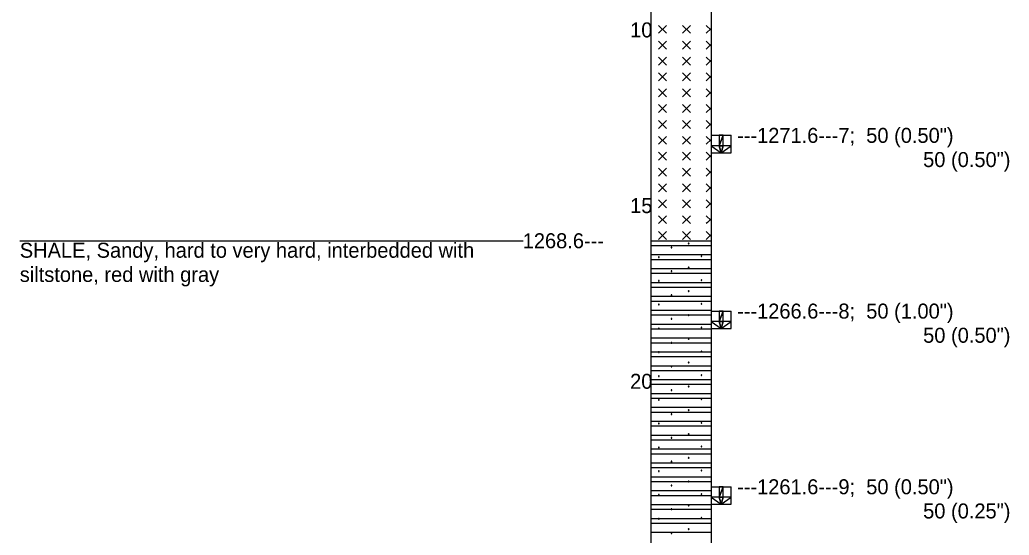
# Model space of a CAD drawing. Extents: x 7 to 126, y 24 to 56.
# Drawn here: x 96.7 to 104.89, y 43.25 to 47.51 of the extents above; entities that cross this region are included whole.
import ezdxf

# ---------------------------------------------------------------- set-up
doc = ezdxf.new("R2010")
doc.units = 0

msp = doc.modelspace()

# ---------------------------------------------------------------- linework, layer by layer
for points in [[(101.9252, 50.3343), (101.9252, 39.2878)], [(102.4252, 50.3343), (102.4252, 39.2878)], [(102.0564, 47.4651), (101.9908, 47.3995)], [(101.9908, 47.4651), (102.0564, 47.3995)], [(102.2533, 47.4651), (102.1876, 47.3995)], [(102.1876, 47.4651), (102.2533, 47.3995)], [(102.3845, 47.4651), (102.4252, 47.4244)], [(102.4252, 47.4402), (102.3845, 47.3995)], [(102.0564, 47.3339), (101.9908, 47.2683)], [(101.9908, 47.3339), (102.0564, 47.2683)], [(102.2533, 47.3339), (102.1876, 47.2683)], [(102.1876, 47.3339), (102.2533, 47.2683)], [(102.3845, 47.3339), (102.4252, 47.2932)], [(102.4252, 47.3089), (102.3845, 47.2683)], [(102.0564, 47.2026), (101.9908, 47.137)], [(101.9908, 47.2026), (102.0564, 47.137)], [(102.2533, 47.2026), (102.1876, 47.137)], [(102.1876, 47.2026), (102.2533, 47.137)], [(102.3845, 47.2026), (102.4252, 47.162)], [(102.4252, 47.1777), (102.3845, 47.137)], [(102.0564, 47.0714), (101.9908, 47.0058)], [(101.9908, 47.0714), (102.0564, 47.0058)], [(102.2533, 47.0714), (102.1876, 47.0058)], [(102.1876, 47.0714), (102.2533, 47.0058)], [(102.3845, 47.0714), (102.4252, 47.0307)], [(102.4252, 47.0465), (102.3845, 47.0058)], [(102.0564, 46.9402), (101.9908, 46.8746)], [(101.9908, 46.9402), (102.0564, 46.8746)], [(102.2533, 46.9402), (102.1876, 46.8746)], [(102.1876, 46.9402), (102.2533, 46.8746)], [(102.3845, 46.9402), (102.4252, 46.8995)], [(102.4252, 46.9152), (102.3845, 46.8746)], [(102.0564, 46.8089), (101.9908, 46.7433)], [(101.9908, 46.8089), (102.0564, 46.7433)], [(102.2533, 46.8089), (102.1876, 46.7433)], [(102.1876, 46.8089), (102.2533, 46.7433)], [(102.3845, 46.8089), (102.4252, 46.7683)], [(102.4252, 46.784), (102.3845, 46.7433)], [(102.0564, 46.6777), (101.9908, 46.6121)], [(101.9908, 46.6777), (102.0564, 46.6121)], [(102.2533, 46.6777), (102.1876, 46.6121)], [(102.1876, 46.6777), (102.2533, 46.6121)], [(102.3845, 46.6777), (102.4252, 46.637)], [(102.4252, 46.6528), (102.3845, 46.6121)], [(102.0564, 46.5465), (101.9908, 46.4808)], [(101.9908, 46.5465), (102.0564, 46.4808)], [(102.2533, 46.5465), (102.1876, 46.4808)], [(102.1876, 46.5465), (102.2533, 46.4808)], [(102.3845, 46.5465), (102.4252, 46.5058)], [(102.4252, 46.5215), (102.3845, 46.4808)], [(102.4252, 46.5552), (102.5918, 46.5552)], [(102.5918, 46.4099), (102.5918, 46.5552)], [(102.0564, 46.4152), (101.9908, 46.3496)], [(101.9908, 46.4152), (102.0564, 46.3496)], [(102.2533, 46.4152), (102.1876, 46.3496)], [(102.1876, 46.4152), (102.2533, 46.3496)], [(102.3845, 46.4152), (102.4252, 46.3746)], [(102.4252, 46.3903), (102.3845, 46.3496)], [(102.4252, 46.4099), (102.5918, 46.4099)], [(102.0564, 46.284), (101.9908, 46.2184)], [(101.9908, 46.284), (102.0564, 46.2184)], [(102.2533, 46.284), (102.1876, 46.2184)], [(102.1876, 46.284), (102.2533, 46.2184)], [(102.3845, 46.284), (102.4252, 46.2433)], [(102.4252, 46.2591), (102.3845, 46.2184)], [(102.0564, 46.1528), (101.9908, 46.0871)], [(101.9908, 46.1528), (102.0564, 46.0871)], [(102.2533, 46.1528), (102.1876, 46.0871)], [(102.1876, 46.1528), (102.2533, 46.0871)], [(102.3845, 46.1528), (102.4252, 46.1121)], [(102.4252, 46.1278), (102.3845, 46.0871)], [(102.0564, 46.0215), (101.9908, 45.9559)], [(101.9908, 46.0215), (102.0564, 45.9559)], [(102.2533, 46.0215), (102.1876, 45.9559)], [(102.1876, 46.0215), (102.2533, 45.9559)], [(102.3845, 46.0215), (102.4252, 45.9808)], [(102.4252, 45.9966), (102.3845, 45.9559)], [(102.0564, 45.8903), (101.9908, 45.8247)], [(101.9908, 45.8903), (102.0564, 45.8247)], [(102.2533, 45.8903), (102.1876, 45.8247)], [(102.1876, 45.8903), (102.2533, 45.8247)], [(102.3845, 45.8903), (102.4252, 45.8496)], [(102.4252, 45.8654), (102.3945, 45.8347), (102.3845, 45.8247)], [(102.0564, 45.7591), (101.9908, 45.6934)], [(101.9908, 45.7591), (102.0564, 45.6934)], [(102.2533, 45.7591), (102.1876, 45.6934)], [(102.1876, 45.7591), (102.2533, 45.6934)], [(102.3845, 45.7591), (102.4162, 45.7273), (102.4252, 45.7184)], [(102.4252, 45.7341), (102.4166, 45.7256), (102.3845, 45.6934)], [(96.7039, 45.6831), (100.8706, 45.6831)], [(101.9252, 45.6831), (102.4252, 45.6831)], [(101.9252, 45.6831), (102.4252, 45.6831)], [(101.9252, 45.6438), (102.4252, 45.6438)], [(102.1002, 45.6273), (102.0986, 45.6302), (102.0953, 45.6302), (102.0937, 45.6274), (102.0953, 45.6245), (102.0986, 45.6245), (102.1002, 45.6273)], [(102.2428, 45.6592), (102.2412, 45.662), (102.2379, 45.662), (102.2363, 45.6592), (102.2379, 45.6564), (102.2412, 45.6564), (102.2428, 45.6592)], [(101.9252, 45.5683), (102.4252, 45.5683)], [(101.9252, 45.5289), (102.4252, 45.5289)], [(101.9956, 45.5484), (101.9939, 45.5512), (101.9907, 45.5512), (101.989, 45.5484), (101.9907, 45.5455), (101.9939, 45.5455), (101.9956, 45.5484)], [(102.3483, 45.5549), (102.3467, 45.5578), (102.3434, 45.5578), (102.3418, 45.5549), (102.3434, 45.552), (102.3467, 45.552), (102.3483, 45.5549)], [(101.9252, 45.4535), (102.4252, 45.4535)], [(102.2428, 45.4623), (102.2412, 45.4652), (102.2379, 45.4652), (102.2363, 45.4623), (102.2379, 45.4595), (102.2412, 45.4595), (102.2428, 45.4623)], [(101.9252, 45.4141), (102.4252, 45.4141)], [(102.1002, 45.4305), (102.0986, 45.4333), (102.0953, 45.4333), (102.0937, 45.4305), (102.0953, 45.4276), (102.0986, 45.4276), (102.1002, 45.4305)], [(101.9252, 45.3387), (102.4252, 45.3387)], [(101.9252, 45.2993), (102.4252, 45.2993)], [(101.9956, 45.3515), (101.9939, 45.3543), (101.9907, 45.3543), (101.989, 45.3515), (101.9907, 45.3486), (101.9939, 45.3486), (101.9956, 45.3515)], [(102.3483, 45.358), (102.3467, 45.3609), (102.3434, 45.3609), (102.3418, 45.358), (102.3434, 45.3552), (102.3467, 45.3552), (102.3483, 45.358)], [(101.9252, 45.2238), (102.4252, 45.2238)], [(102.1002, 45.2336), (102.0986, 45.2365), (102.0953, 45.2365), (102.0937, 45.2337), (102.0953, 45.2308), (102.0986, 45.2308), (102.1002, 45.2336)], [(102.2428, 45.2655), (102.2412, 45.2683), (102.2379, 45.2683), (102.2363, 45.2655), (102.2379, 45.2627), (102.2412, 45.2627), (102.2428, 45.2655)], [(101.9252, 45.1845), (102.4252, 45.1845)], [(101.9956, 45.1547), (101.9939, 45.1575), (101.9907, 45.1575), (101.989, 45.1547), (101.9907, 45.1518), (101.9939, 45.1518), (101.9956, 45.1547)], [(102.3483, 45.1612), (102.3467, 45.1641), (102.3434, 45.1641), (102.3418, 45.1612), (102.3434, 45.1583), (102.3467, 45.1583), (102.3483, 45.1612)], [(101.9252, 45.109), (102.4252, 45.109)], [(101.9252, 45.0696), (102.4252, 45.0696)], [(102.1002, 45.0368), (102.0986, 45.0396), (102.0953, 45.0396), (102.0937, 45.0368), (102.0953, 45.0339), (102.0986, 45.0339), (102.1002, 45.0368)], [(102.2428, 45.0686), (102.2412, 45.0715), (102.2379, 45.0715), (102.2363, 45.0686), (102.2379, 45.0658), (102.2412, 45.0658), (102.2428, 45.0686)], [(102.4252, 45.1018), (102.5918, 45.1018)], [(102.5918, 44.9564), (102.5918, 45.1018)], [(101.9252, 44.9942), (102.4252, 44.9942)], [(101.9252, 44.9548), (102.4252, 44.9548)], [(101.9956, 44.9578), (101.9939, 44.9606), (101.9907, 44.9606), (101.989, 44.9578), (101.9907, 44.9549), (101.9939, 44.9549), (101.9956, 44.9578)], [(102.3483, 44.9643), (102.3467, 44.9672), (102.3434, 44.9672), (102.3418, 44.9643), (102.3434, 44.9615), (102.3467, 44.9615), (102.3483, 44.9643)], [(102.4252, 44.9564), (102.5918, 44.9564)], [(101.9252, 44.8793), (102.4252, 44.8793)], [(102.2428, 44.8718), (102.2412, 44.8746), (102.2379, 44.8746), (102.2363, 44.8718), (102.2379, 44.869), (102.2412, 44.869), (102.2428, 44.8718)], [(101.9252, 44.84), (102.4252, 44.84)], [(102.1002, 44.8399), (102.0986, 44.8428), (102.0953, 44.8428), (102.0937, 44.84), (102.0953, 44.8371), (102.0986, 44.8371), (102.1002, 44.8399)], [(101.9252, 44.7645), (102.4252, 44.7645)], [(101.9252, 44.7251), (102.4252, 44.7251)], [(101.9956, 44.761), (101.9939, 44.7638), (101.9907, 44.7638), (101.989, 44.761), (101.9907, 44.7581), (101.9939, 44.7581), (101.9956, 44.761)], [(102.3483, 44.7675), (102.3467, 44.7704), (102.3434, 44.7704), (102.3418, 44.7675), (102.3434, 44.7646), (102.3467, 44.7646), (102.3483, 44.7675)], [(101.9252, 44.6497), (102.4252, 44.6497)], [(102.1002, 44.6431), (102.0986, 44.6459), (102.0953, 44.6459), (102.0937, 44.6431), (102.0953, 44.6402), (102.0986, 44.6402), (102.1002, 44.6431)], [(102.2428, 44.6749), (102.2412, 44.6778), (102.2379, 44.6778), (102.2363, 44.6749), (102.2379, 44.6721), (102.2412, 44.6721), (102.2428, 44.6749)], [(101.9252, 44.6103), (102.4252, 44.6103)], [(101.9956, 44.5641), (101.9939, 44.5669), (101.9907, 44.5669), (101.989, 44.5641), (101.9907, 44.5612), (101.9939, 44.5612), (101.9956, 44.5641)], [(102.3483, 44.5706), (102.3467, 44.5735), (102.3434, 44.5735), (102.3418, 44.5706), (102.3434, 44.5678), (102.3467, 44.5678), (102.3483, 44.5706)], [(101.9252, 44.5349), (102.4252, 44.5349)], [(101.9252, 44.4955), (102.4252, 44.4955)], [(102.2428, 44.4781), (102.2412, 44.4809), (102.2379, 44.4809), (102.2363, 44.4781), (102.2379, 44.4753), (102.2412, 44.4753), (102.2428, 44.4781)], [(101.9252, 44.42), (102.4252, 44.42)], [(101.9252, 44.3807), (102.4252, 44.3807)], [(102.1002, 44.4462), (102.0986, 44.4491), (102.0953, 44.4491), (102.0937, 44.4463), (102.0953, 44.4434), (102.0986, 44.4434), (102.1002, 44.4462)], [(101.9252, 44.3052), (102.4252, 44.3052)], [(101.9956, 44.3673), (101.9939, 44.3701), (101.9907, 44.3701), (101.989, 44.3673), (101.9907, 44.3644), (101.9939, 44.3644), (101.9956, 44.3673)], [(102.3483, 44.3738), (102.3467, 44.3767), (102.3434, 44.3767), (102.3418, 44.3738), (102.3434, 44.3709), (102.3467, 44.3709), (102.3483, 44.3738)], [(101.9252, 44.2658), (102.4252, 44.2658)], [(102.1002, 44.2494), (102.0986, 44.2522), (102.0953, 44.2522), (102.0937, 44.2494), (102.0953, 44.2465), (102.0986, 44.2465), (102.1002, 44.2494)], [(102.2428, 44.2812), (102.2412, 44.2841), (102.2379, 44.2841), (102.2363, 44.2812), (102.2379, 44.2784), (102.2412, 44.2784), (102.2428, 44.2812)], [(101.9252, 44.1904), (102.4252, 44.1904)], [(101.9252, 44.151), (102.4252, 44.151)], [(101.9956, 44.1704), (101.9939, 44.1732), (101.9907, 44.1732), (101.989, 44.1704), (101.9907, 44.1675), (101.9939, 44.1675), (101.9956, 44.1704)], [(102.3483, 44.1769), (102.3467, 44.1798), (102.3434, 44.1798), (102.3418, 44.1769), (102.3434, 44.1741), (102.3467, 44.1741), (102.3483, 44.1769)], [(101.9252, 44.0755), (102.4252, 44.0755)], [(102.1002, 44.0525), (102.0986, 44.0554), (102.0953, 44.0554), (102.0937, 44.0526), (102.0953, 44.0497), (102.0986, 44.0497), (102.1002, 44.0525)], [(102.2428, 44.0844), (102.2412, 44.0872), (102.2379, 44.0872), (102.2363, 44.0844), (102.2379, 44.0816), (102.2412, 44.0816), (102.2428, 44.0844)], [(101.9252, 44.0362), (102.4252, 44.0362)], [(101.9956, 43.9736), (101.9939, 43.9764), (101.9907, 43.9764), (101.989, 43.9736), (101.9907, 43.9707), (101.9939, 43.9707), (101.9956, 43.9736)], [(102.3483, 43.9801), (102.3467, 43.983), (102.3434, 43.983), (102.3418, 43.9801), (102.3434, 43.9772), (102.3467, 43.9772), (102.3483, 43.9801)], [(101.9252, 43.9607), (102.4252, 43.9607)], [(101.9252, 43.9213), (102.4252, 43.9213)], [(102.2428, 43.8875), (102.2412, 43.8904), (102.2379, 43.8904), (102.2363, 43.8875), (102.2379, 43.8847), (102.2412, 43.8847), (102.2428, 43.8875)], [(101.9252, 43.8459), (102.4252, 43.8459)], [(101.9252, 43.8065), (102.4252, 43.8065)], [(102.1002, 43.8557), (102.0986, 43.8585), (102.0953, 43.8585), (102.0937, 43.8557), (102.0953, 43.8528), (102.0986, 43.8528), (102.1002, 43.8557)], [(101.9252, 43.731), (102.4252, 43.731)], [(101.9956, 43.7767), (101.9939, 43.7795), (101.9907, 43.7795), (101.989, 43.7767), (101.9907, 43.7738), (101.9939, 43.7738), (101.9956, 43.7767)], [(102.3483, 43.7832), (102.3467, 43.7861), (102.3434, 43.7861), (102.3418, 43.7832), (102.3434, 43.7804), (102.3467, 43.7804), (102.3483, 43.7832)], [(101.9252, 43.6917), (102.4252, 43.6917)], [(102.1002, 43.6588), (102.0986, 43.6617), (102.0953, 43.6617), (102.0937, 43.6589), (102.0953, 43.656), (102.0986, 43.656), (102.1002, 43.6588)], [(102.2428, 43.6907), (102.2412, 43.6935), (102.2379, 43.6935), (102.2363, 43.6907), (102.2379, 43.6879), (102.2412, 43.6879), (102.2428, 43.6907)], [(102.4252, 43.6483), (102.5918, 43.6483)], [(102.5918, 43.5029), (102.5918, 43.6483)], [(101.9252, 43.6162), (102.4252, 43.6162)], [(101.9252, 43.5768), (102.4252, 43.5768)], [(101.9956, 43.5799), (101.9939, 43.5827), (101.9907, 43.5827), (101.989, 43.5799), (101.9907, 43.577), (101.9939, 43.577), (101.9956, 43.5799)], [(102.3483, 43.5864), (102.3467, 43.5893), (102.3434, 43.5893), (102.3418, 43.5864), (102.3434, 43.5835), (102.3467, 43.5835), (102.3483, 43.5864)], [(101.9252, 43.5014), (102.4252, 43.5014)], [(102.2428, 43.4938), (102.2412, 43.4967), (102.2379, 43.4967), (102.2363, 43.4938), (102.2379, 43.491), (102.2412, 43.491), (102.2428, 43.4938)], [(102.4252, 43.5029), (102.5918, 43.5029)], [(101.9252, 43.462), (102.4252, 43.462)], [(102.1002, 43.462), (102.0986, 43.4648), (102.0953, 43.4648), (102.0937, 43.462), (102.0953, 43.4591), (102.0986, 43.4591), (102.1002, 43.462)], [(101.9252, 43.3866), (102.4252, 43.3866)], [(101.9252, 43.3472), (102.4252, 43.3472)], [(101.9956, 43.383), (101.9939, 43.3858), (101.9907, 43.3858), (101.989, 43.383), (101.9907, 43.3801), (101.9939, 43.3801), (101.9956, 43.383)], [(102.3483, 43.3895), (102.3467, 43.3924), (102.3434, 43.3924), (102.3418, 43.3895), (102.3434, 43.3867), (102.3467, 43.3867), (102.3483, 43.3895)], [(101.9252, 43.2717), (102.4252, 43.2717)], [(102.1002, 43.2651), (102.0986, 43.268), (102.0953, 43.268), (102.0937, 43.2652), (102.0953, 43.2623), (102.0986, 43.2623), (102.1002, 43.2651)], [(102.2428, 43.297), (102.2412, 43.2998), (102.2379, 43.2998), (102.2363, 43.297), (102.2379, 43.2942), (102.2412, 43.2942), (102.2428, 43.297)]]:
    msp.add_lwpolyline(points)
for points in [[(102.4918, 46.468), (102.5252, 46.468), (102.5252, 46.5552), (102.4918, 46.468)], [(102.4918, 46.468), (102.5252, 46.5552), (102.4918, 46.5552), (102.4918, 46.468)], [(102.4918, 46.468), (102.4252, 46.468), (102.5085, 46.4099), (102.4918, 46.468)], [(102.4918, 46.468), (102.5085, 46.4099), (102.5252, 46.468), (102.4918, 46.468)], [(102.5085, 46.4099), (102.5918, 46.468), (102.5252, 46.468), (102.5085, 46.4099)], [(102.4918, 45.0145), (102.5252, 45.0145), (102.5252, 45.1018), (102.4918, 45.0145)], [(102.4918, 45.0145), (102.5252, 45.1018), (102.4918, 45.1018), (102.4918, 45.0145)], [(102.4918, 45.0145), (102.4252, 45.0145), (102.5085, 44.9564), (102.4918, 45.0145)], [(102.4918, 45.0145), (102.5085, 44.9564), (102.5252, 45.0145), (102.4918, 45.0145)], [(102.5085, 44.9564), (102.5918, 45.0145), (102.5252, 45.0145), (102.5085, 44.9564)], [(102.4918, 43.5611), (102.5252, 43.5611), (102.5252, 43.6483), (102.4918, 43.5611)], [(102.4918, 43.5611), (102.5252, 43.6483), (102.4918, 43.6483), (102.4918, 43.5611)], [(102.4918, 43.5611), (102.4252, 43.5611), (102.5085, 43.5029), (102.4918, 43.5611)], [(102.4918, 43.5611), (102.5085, 43.5029), (102.5252, 43.5611), (102.4918, 43.5611)], [(102.5085, 43.5029), (102.5918, 43.5611), (102.5252, 43.5611), (102.5085, 43.5029)]]:
    msp.add_lwpolyline(points, close=True)

# ---------------------------------------------------------------- texts
for s, p in [('10', (101.7548, 47.3653)), ('---1271.6---7;  50 (0.50")', (102.6398, 46.4928)), ('50 (0.50")', (104.1797, 46.2928)), ('15', (101.7548, 45.9118)), ('1268.6---', (100.8657, 45.6211)), ('SHALE, Sandy, hard to very hard, interbedded with', (96.7039, 45.5425)), ('siltstone, red with gray', (96.7039, 45.3425)), ('---1266.6---8;  50 (1.00")', (102.6398, 45.0393)), ('50 (0.50")', (104.1797, 44.8393)), ('20', (101.7548, 44.4584)), ('---1261.6---9;  50 (0.50")', (102.6398, 43.5859)), ('50 (0.25")', (104.1797, 43.3859))]:
    msp.add_text(s, height=0.124).set_placement(p)

doc.saveas('drawing.dxf')
